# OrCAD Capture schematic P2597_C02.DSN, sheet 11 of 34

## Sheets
11 23_12V BOOST: size Custom
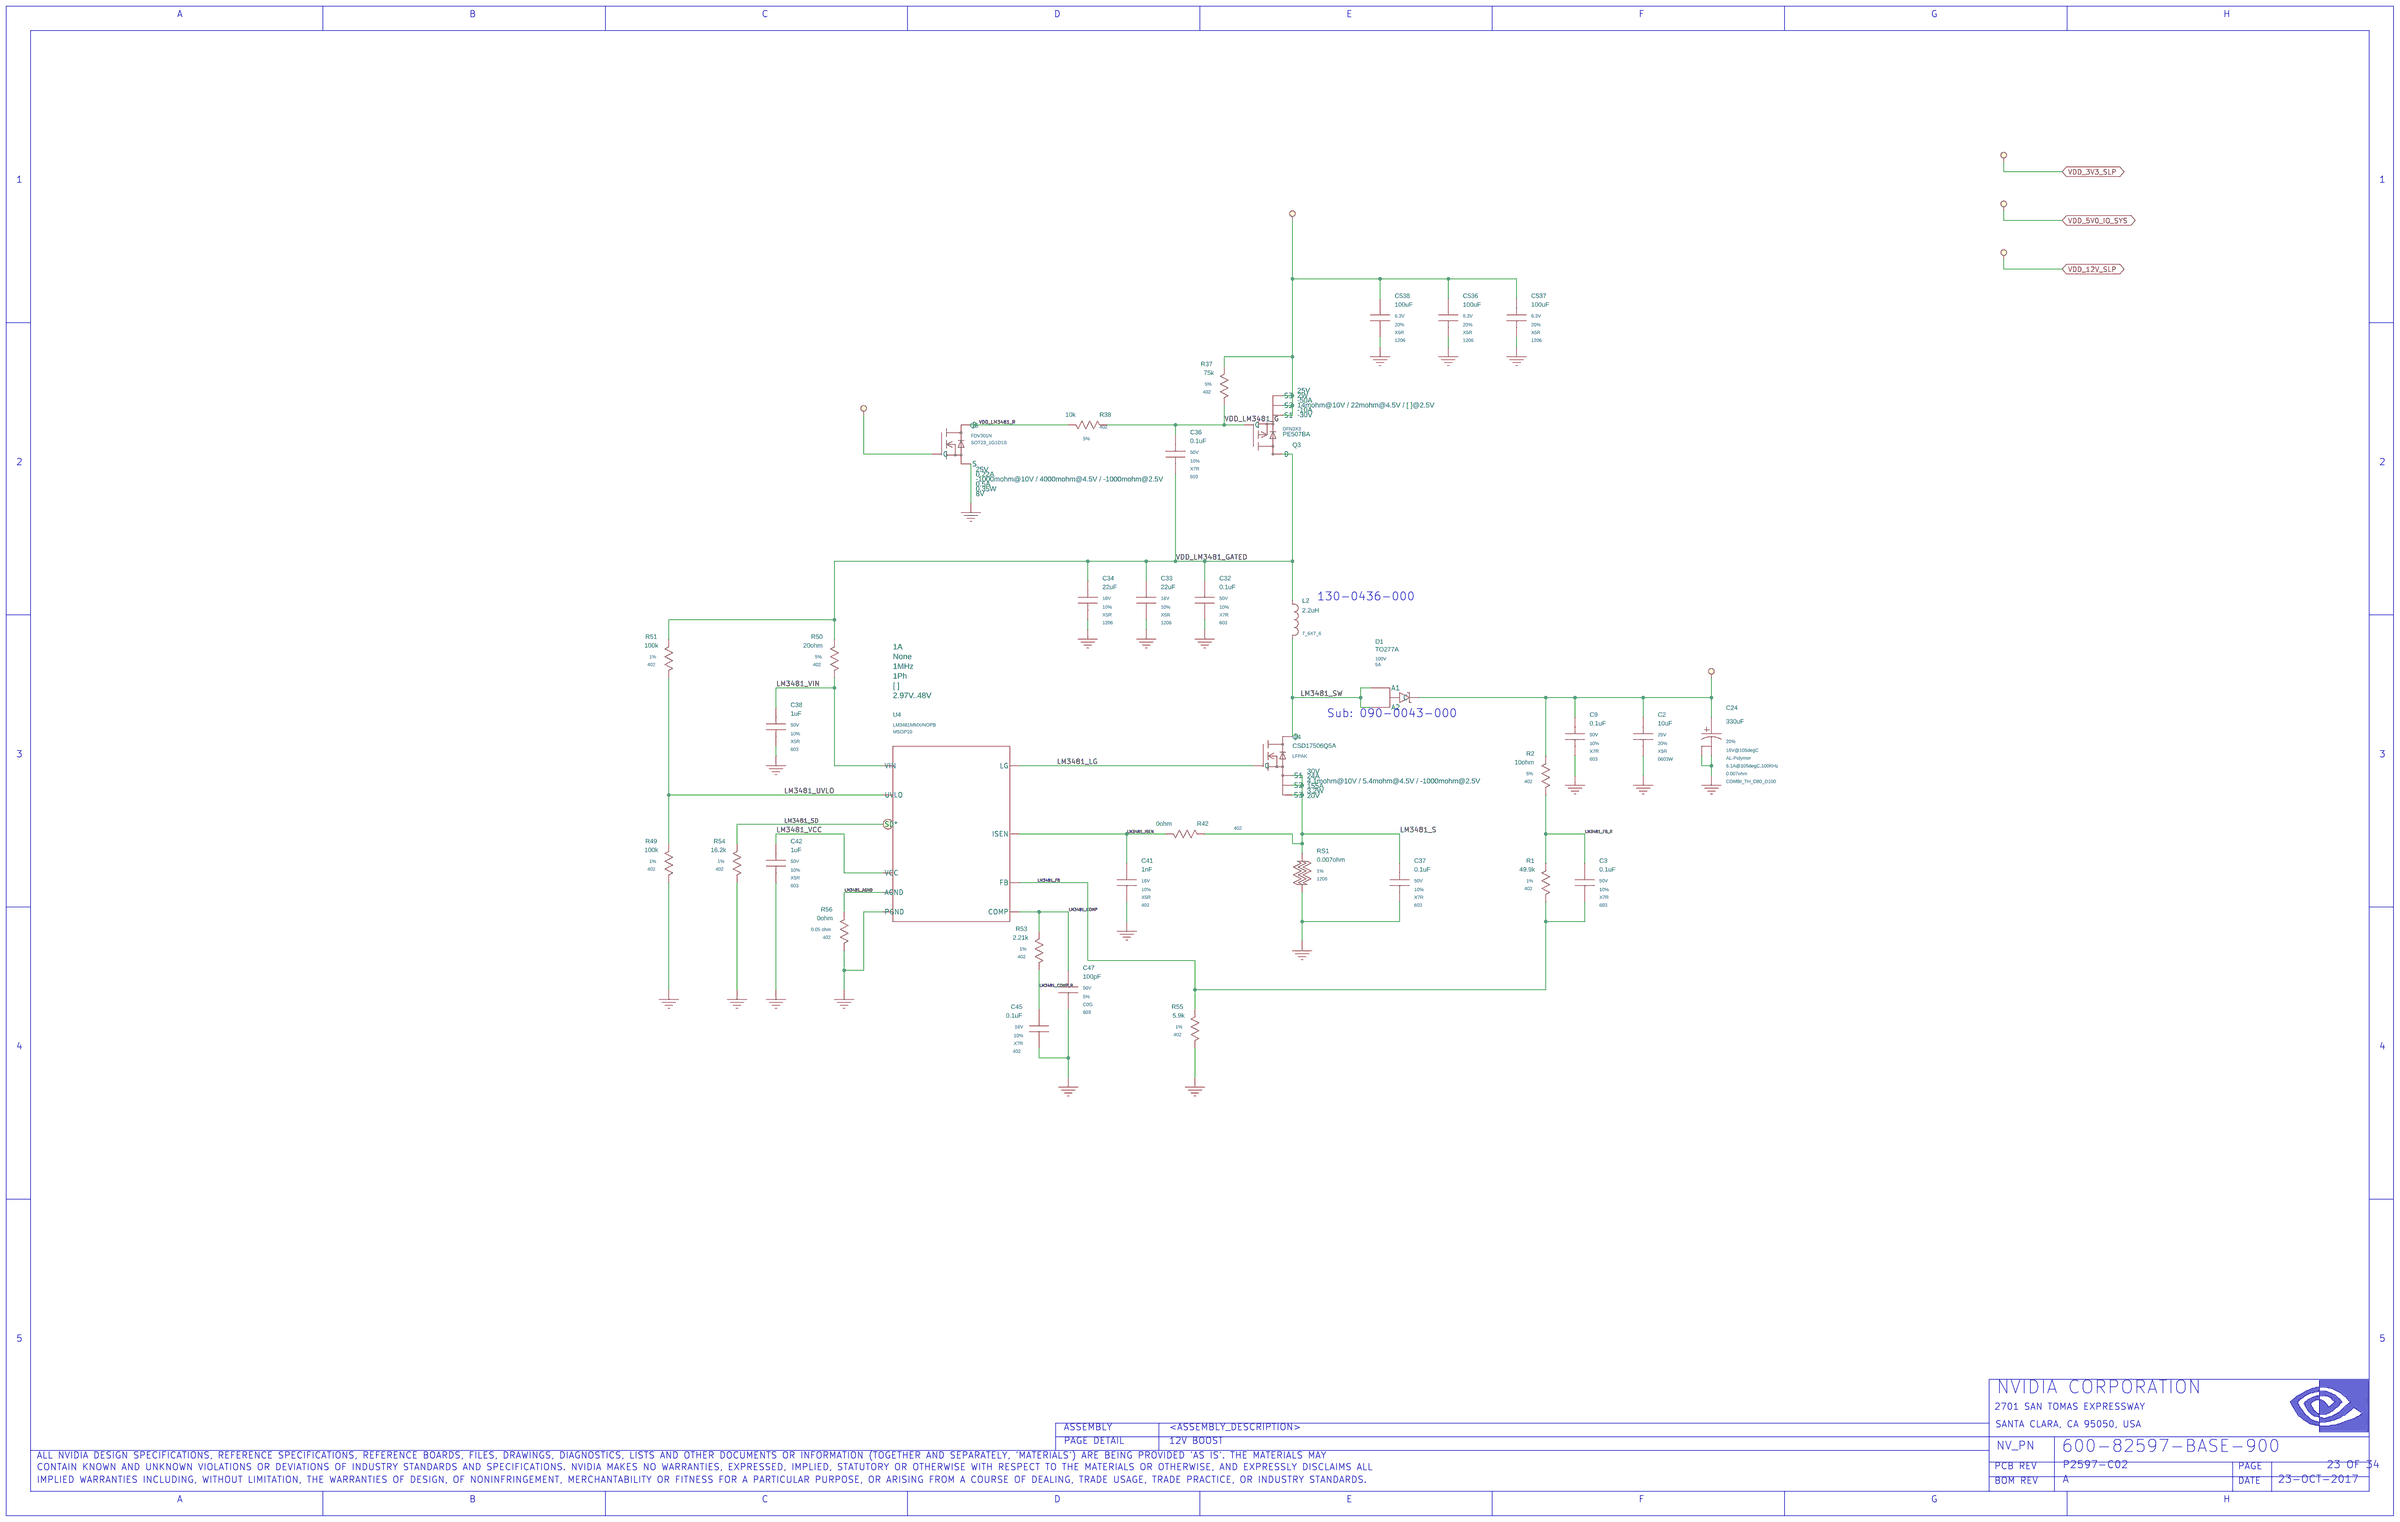
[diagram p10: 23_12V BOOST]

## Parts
C2  10uF  [0603_LARGE]
C3  0.1uF  [603]
C9  0.1uF  [603]
C24  330uF  [MULTI_CAP_TH_D080P035_D100P050]
C32  0.1uF  [603]
C33  22uF  [1206]
C34  22uF  [1206]
C36  0.1uF  [603]
C37  0.1uF  [603]
C38  1uF  [603]
C41  1nF  [402]
C42  1uF  [603]
C45  0.1uF  [402]
C47  100pF  [603]
C536  100uF  [1206]
C537  100uF  [1206]
C538  100uF  [1206]
D1  D_SCHOTTKY_3PIN_AA  [DIODE_SMD_TO277A]
L2  2.2uH  [IND_NONRKO_SMD_076X076]
Q3  Q_FET_P_ENH  [DFET_SMD_032X033]
Q4  Q_FET_N_ENH  [MULTI_SMD_SOT669_LFPAK_B]
Q5  Q_FET_N_ENH  [SOT23]
R1  49.9k  [402]
R2  10ohm  [402]
R37  75k  [402]
R38  10k  [402]
R42  0ohm  [402]
R49  100k  [402]
R50  20ohm  [402]
R51  100k  [402]
R53  2.21k  [402]
R54  16.2k  [402]
R55  5.9k  [402]
R56  0ohm  [402]
RS1  0.007ohm  [1206]
U4  1.275V  [XSOP10_P050_030X030]

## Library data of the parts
C2 = C: ASSEMBLY: VR_12V; CDS_LIB: discrete; CDS_PART_NAME: C_0603W-10UF,X5R,20%,25V,032-0421-000; CDS_PHYS_PART_NAME: C_0603W-10UF,X5R,20%,25V,032-0421-000-032-0421-000,10UF; CDS_SEC: 1; DEVICE_TYPENAME: C_0603W-10UFX5R2025V032-0421-000-032-0421-00010UF; DRAWING: @P2597_C02_LIB.P2597_C02(SCH_1):PAGE23; MAT: X5R; MAX_VOLTAGE: 25V; NV_PN: 032-0421-000; PACK_TYPE: 0603W; PATH: I43; PHYS_PAGE: 23; ROT: 0; SEC: 1; SIGNAL_MODEL: nv_cap; TOL: 20%; VER: 1; XY: (-3750,3850)
C3 = C: ASSEMBLY: VR_12V; CDS_LIB: discrete; CDS_PART_NAME: C_0603-0.1UF,X7R,10%,50V,036-0050-000; CDS_PHYS_PART_NAME: C_0603-0.1UF,X7R,10%,50V,036-0050-000-0.1UF,036-0050-000; CDS_SEC: 1; DEVICE_TYPENAME: C_0603-01UFX7R1050V036-0050-000-01UF036-0050-000; DRAWING: @P2597_C02_LIB.P2597_C02(SCH_1):PAGE23; MAT: X7R; MAX_VOLTAGE: 50V; NV_PN: 036-0050-000; PATH: I27; PHYS_PAGE: 23; ROT: 0; SEC: 1; SIGNAL_MODEL: nv_cap; TOL: 10%; VER: 1; XY: (-4050,3100)
C9 = C: ASSEMBLY: VR_12V; CDS_LIB: discrete; CDS_PART_NAME: C_0603-0.1UF,X7R,10%,50V,036-0050-000; CDS_PHYS_PART_NAME: C_0603-0.1UF,X7R,10%,50V,036-0050-000-0.1UF,036-0050-000; CDS_SEC: 1; DEVICE_TYPENAME: C_0603-01UFX7R1050V036-0050-000-01UF036-0050-000; DRAWING: @P2597_C02_LIB.P2597_C02(SCH_1):PAGE23; MAT: X7R; MAX_VOLTAGE: 50V; NV_PN: 036-0050-000; PATH: I40; PHYS_PAGE: 23; ROT: 0; SEC: 1; SIGNAL_MODEL: nv_cap; TOL: 10%; VER: 1; XY: (-4100,3850)
C24 = C_POL#1: ASSEMBLY: VR_12V; CDS_LIB: discrete; CDS_PART_NAME: C_POL_COMBI_TH_D80_D100-330UF,AL-POLYMER,20%,16V@105DEGC,0.007OHM,9.999UH,6.1A@105DEGC,100KHZ,041-0065-000; CDS_PHYS_PART_NAME: C_POL_COMBI_TH_D80_D100-330UF,AL-POLYMER,20%,16V@105DEGC,0.007OHM,9.999UH,6.1A@105DEGC,100KHZ,041-0065-000-041-0065-000,330UF; CDS_SEC: 1; CHIPS_PART_NAME: C_POL; DEVICE_TYPENAME: C_POL_COMBI_TH_D80_D100-330UFAL-POLYMER2016V105DEGC0007OHM9999UH61A105DEGC100KHZ041-0065-000-041-0065-000330UF; DRAWING: @P2597_C02_LIB.P2597_C02(SCH_1):PAGE23; ESL: 9.999uH; ESR: 0.007ohm; MAT: AL-Polymer; MAX_VOLTAGE: 16V@105degC; NV_PN: 041-0065-000; PACK_TYPE: COMBI_TH_D80_D100; PATH: I44; PHYS_PAGE: 23; RIPPLE_CURRENT: 6.1A@105degC,100KHz; ROT: 0; SEC: 1; SEC_TYPE: COMBI_TH_D80_D100; SIGNAL_MODEL: nv_capp_3p; TOL: 20%; VER: 3; XY: (-3400,3850)
C32 = C: ASSEMBLY: VR_12V; CDS_LIB: discrete; CDS_PART_NAME: C_0603-0.1UF,X7R,10%,50V,036-0050-000; CDS_PHYS_PART_NAME: C_0603-0.1UF,X7R,10%,50V,036-0050-000-0.1UF,036-0050-000; CDS_SEC: 1; DEVICE_TYPENAME: C_0603-01UFX7R1050V036-0050-000-01UF036-0050-000; DRAWING: @P2597_C02_LIB.P2597_C02(SCH_1):PAGE23; MAT: X7R; MAX_VOLTAGE: 50V; NV_PN: 036-0050-000; PATH: I35; PHYS_PAGE: 23; ROT: 0; SEC: 1; SIGNAL_MODEL: nv_cap; TOL: 10%; VER: 1; XY: (-6000,4550)
C33 = C: ASSEMBLY: VR_12V; CDS_LIB: discrete; CDS_PART_NAME: C_1206-22UF,X5R,10%,16V,039-0158-000; CDS_PHYS_PART_NAME: C_1206-22UF,X5R,10%,16V,039-0158-000-039-0158-000,22UF; CDS_SEC: 1; DEVICE_TYPENAME: C_1206-22UFX5R1016V039-0158-000-039-0158-00022UF; DRAWING: @P2597_C02_LIB.P2597_C02(SCH_1):PAGE23; MAT: X5R; MAX_VOLTAGE: 16V; NV_PN: 039-0158-000; PATH: I33; PHYS_PAGE: 23; ROT: 0; SEC: 1; SIGNAL_MODEL: nv_cap; TOL: 10%; VER: 1; XY: (-6300,4550)
C34 = C: ASSEMBLY: VR_12V; CDS_LIB: discrete; CDS_PART_NAME: C_1206-22UF,X5R,10%,16V,039-0158-000; CDS_PHYS_PART_NAME: C_1206-22UF,X5R,10%,16V,039-0158-000-039-0158-000,22UF; CDS_SEC: 1; DEVICE_TYPENAME: C_1206-22UFX5R1016V039-0158-000-039-0158-00022UF; DRAWING: @P2597_C02_LIB.P2597_C02(SCH_1):PAGE23; MAT: X5R; MAX_VOLTAGE: 16V; NV_PN: 039-0158-000; PATH: I28; PHYS_PAGE: 23; ROT: 0; SEC: 1; SIGNAL_MODEL: nv_cap; TOL: 10%; VER: 1; XY: (-6600,4550)
C36 = C: ASSEMBLY: VR_12V; CDS_LIB: discrete; CDS_PART_NAME: C_0603-0.1UF,X7R,10%,50V,036-0050-000; CDS_PHYS_PART_NAME: C_0603-0.1UF,X7R,10%,50V,036-0050-000-0.1UF,036-0050-000; CDS_SEC: 1; DEVICE_TYPENAME: C_0603-01UFX7R1050V036-0050-000-01UF036-0050-000; DRAWING: @P2597_C02_LIB.P2597_C02(SCH_1):PAGE23; MAT: X7R; MAX_VOLTAGE: 50V; NV_PN: 036-0050-000; PATH: I55; PHYS_PAGE: 23; ROT: 0; SEC: 1; SIGNAL_MODEL: nv_cap; TOL: 10%; VER: 1; XY: (-6150,5300)
C37 = C: ASSEMBLY: VR_12V; CDS_LIB: discrete; CDS_PART_NAME: C_0603-0.1UF,X7R,10%,50V,036-0050-000; CDS_PHYS_PART_NAME: C_0603-0.1UF,X7R,10%,50V,036-0050-000-0.1UF,036-0050-000; CDS_SEC: 1; DEVICE_TYPENAME: C_0603-01UFX7R1050V036-0050-000-01UF036-0050-000; DRAWING: @P2597_C02_LIB.P2597_C02(SCH_1):PAGE23; MAT: X7R; MAX_VOLTAGE: 50V; NV_PN: 036-0050-000; PATH: I25; PHYS_PAGE: 23; ROT: 0; SEC: 1; SIGNAL_MODEL: nv_cap; TOL: 10%; VER: 1; XY: (-5000,3100)
C38 = C: ASSEMBLY: VR_12V; CDS_LIB: discrete; CDS_PART_NAME: C_0603-1UF,X5R,10%,50V,039-0222-000; CDS_PHYS_PART_NAME: C_0603-1UF,X5R,10%,50V,039-0222-000-039-0222-000,1UF; CDS_SEC: 1; DEVICE_TYPENAME: C_0603-1UFX5R1050V039-0222-000-039-0222-0001UF; DRAWING: @P2597_C02_LIB.P2597_C02(SCH_1):PAGE23; MAT: X5R; MAX_VOLTAGE: 50V; NV_PN: 039-0222-000; PATH: I12; PHYS_PAGE: 23; ROT: 0; SEC: 1; SIGNAL_MODEL: nv_cap; TOL: 10%; VER: 1; XY: (-8200,3900)
C41 = C: ASSEMBLY: VR_12V; CDS_LIB: discrete; CDS_PART_NAME: C_0402-1NF,X5R,10%,16V,039-0023-000; CDS_PHYS_PART_NAME: C_0402-1NF,X5R,10%,16V,039-0023-000-039-0023-000,1NF; CDS_SEC: 1; DEVICE_TYPENAME: C_0402-1NFX5R1016V039-0023-000-039-0023-0001NF; DRAWING: @P2597_C02_LIB.P2597_C02(SCH_1):PAGE23; MAT: X5R; MAX_VOLTAGE: 16V; NV_PN: 039-0023-000; PATH: I20; PHYS_PAGE: 23; ROT: 0; SEC: 1; SIGNAL_MODEL: nv_cap; TOL: 10%; VER: 1; XY: (-6400,3100)
C42 = C: ASSEMBLY: VR_12V; CDS_LIB: discrete; CDS_PART_NAME: C_0603-1UF,X5R,10%,50V,039-0222-000; CDS_PHYS_PART_NAME: C_0603-1UF,X5R,10%,50V,039-0222-000-039-0222-000,1UF; CDS_SEC: 1; DEVICE_TYPENAME: C_0603-1UFX5R1050V039-0222-000-039-0222-0001UF; DRAWING: @P2597_C02_LIB.P2597_C02(SCH_1):PAGE23; MAT: X5R; MAX_VOLTAGE: 50V; NV_PN: 039-0222-000; PATH: I5; PHYS_PAGE: 23; ROT: 0; SEC: 1; SIGNAL_MODEL: nv_cap; TOL: 10%; VER: 1; XY: (-8200,3200)
C45 = C: ASSEMBLY: VR_12V; CDS_LIB: discrete; CDS_PART_NAME: C_0402-0.1UF,X7R,10%,16V,036-0014-000; CDS_PHYS_PART_NAME: C_0402-0.1UF,X7R,10%,16V,036-0014-000-0.1UF,036-0014-000; CDS_SEC: 1; DEVICE_TYPENAME: C_0402-01UFX7R1016V036-0014-000-01UF036-0014-000; DRAWING: @P2597_C02_LIB.P2597_C02(SCH_1):PAGE23; MAT: X7R; MAX_VOLTAGE: 16V; NV_PN: 036-0014-000; PATH: I62; PHYS_PAGE: 23; ROT: 2; SEC: 1; SIGNAL_MODEL: nv_cap; TOL: 10%; VER: 1; XY: (-6850,2350)
C47 = C: ASSEMBLY: VR_12V; CDS_LIB: discrete; CDS_PART_NAME: C_0603-100PF,C0G,5%,50V,035-0040-000; CDS_PHYS_PART_NAME: C_0603-100PF,C0G,5%,50V,035-0040-000-035-0040-000,100PF; CDS_SEC: 1; DEVICE_TYPENAME: C_0603-100PFC0G550V035-0040-000-035-0040-000100PF; DRAWING: @P2597_C02_LIB.P2597_C02(SCH_1):PAGE23; MAT: C0G; MAX_VOLTAGE: 50V; NV_PN: 035-0040-000; PATH: I61; PHYS_PAGE: 23; ROT: 0; SEC: 1; SIGNAL_MODEL: nv_cap; TOL: 5%; VER: 1; XY: (-6700,2550)
C536 = C: ASSEMBLY: VR_12V; CDS_LIB: discrete; CDS_PART_NAME: C_1206-100UF,X5R,20%,6.3V,039-0148-000; CDS_PHYS_PART_NAME: C_1206-100UF,X5R,20%,6.3V,039-0148-000-039-0148-000,100UF; CDS_SEC: 1; DEVICE_TYPENAME: C_1206-100UFX5R2063V039-0148-000-039-0148-000100UF; DRAWING: @P2597_C02_LIB.P2597_C02(SCH_1):PAGE23; MAT: X5R; MAX_VOLTAGE: 6.3V; NV_PN: 039-0148-000; PATH: I69; PHYS_PAGE: 23; ROT: 0; SEC: 1; SIGNAL_MODEL: nv_cap; TOL: 20%; VER: 1; XY: (-4750,6000)
C537 = C: ASSEMBLY: VR_12V; CDS_LIB: discrete; CDS_PART_NAME: C_1206-100UF,X5R,20%,6.3V,039-0148-000; CDS_PHYS_PART_NAME: C_1206-100UF,X5R,20%,6.3V,039-0148-000-039-0148-000,100UF; CDS_SEC: 1; DEVICE_TYPENAME: C_1206-100UFX5R2063V039-0148-000-039-0148-000100UF; DRAWING: @P2597_C02_LIB.P2597_C02(SCH_1):PAGE23; MAT: X5R; MAX_VOLTAGE: 6.3V; NV_PN: 039-0148-000; PATH: I73; PHYS_PAGE: 23; ROT: 0; SEC: 1; SIGNAL_MODEL: nv_cap; TOL: 20%; VER: 1; XY: (-4400,6000)
C538 = C: ASSEMBLY: VR_12V; CDS_LIB: discrete; CDS_PART_NAME: C_1206-100UF,X5R,20%,6.3V,039-0148-000; CDS_PHYS_PART_NAME: C_1206-100UF,X5R,20%,6.3V,039-0148-000-039-0148-000,100UF; CDS_SEC: 1; DEVICE_TYPENAME: C_1206-100UFX5R2063V039-0148-000-039-0148-000100UF; DRAWING: @P2597_C02_LIB.P2597_C02(SCH_1):PAGE23; MAT: X5R; MAX_VOLTAGE: 6.3V; NV_PN: 039-0148-000; PATH: I71; PHYS_PAGE: 23; ROT: 0; SEC: 1; SIGNAL_MODEL: nv_cap; TOL: 20%; VER: 1; XY: (-5100,6000)
D1 = D_SCHOTTKY_3PIN_AA: ASSEMBLY: VR_12V; CDS_LIB: discrete; CDS_PART_NAME: D_SCHOTTKY_3PIN_AA_SMPC-TO277A,1 PAIR - COMMON CATHODE,100V,150A,0.88V@5A,5A,090-0043-000; CDS_PHYS_PART_NAME: D_SCHOTTKY_3PIN_AA_SMPC-TO277A,1 PAIR - COMMON CATHODE,100V,150A,0.88V@5A,5A,090-0043-000-090-0043-000; CDS_SEC: 1; CONFIGURATION: 1 Pair - Common Cathode; CONTINUOUS_CURRENT: 5A; DEVICE_TYPENAME: D_SCHOTTKY_3PIN_AA_SMPC-TO277A1PAIR-COMMONCATHODE100V150A088V5A5A090-0043-000-090-0043-000; DRAWING: @P2597_C02_LIB.P2597_C02(SCH_1):PAGE23; FORWARD_VOLTAGE: 0.88V@5A; MAX_CURRENT: 150A; MAX_VOLTAGE: 100V; NV_NAME: TO277A; NV_PN: 090-0043-000; PACK_TYPE: SMPC; PATH: I68; PHYS_PAGE: 23; ROT: 0; SEC: 1; SEC_TYPE: SMPC; VER: 2; XY: (-5050,4050)
L2 = L#1: ACOUSTIC_MARGIN: 0decibel; ASSEMBLY: VR_12V; CDS_LIB: discrete; CDS_PART_NAME: L_7_6X7_6-2.2UH,ALLOY CORE,20%,10A,10A,0.0132OHM,[ ]@[ ],[ ],0DECIBEL,130-0436-000; CDS_PHYS_PART_NAME: L_7_6X7_6-2.2UH,ALLOY CORE,20%,10A,10A,0.0132OHM,[ ]@[ ],[ ],0DECIBEL,130-0436-000-130-0436-000,2.2UH; CDS_SEC: 1; CHIPS_PART_NAME: L; CONTINUOUS_CURRENT: 10A; DC_RESISTANCE: 0.0132ohm; DEVICE_TYPENAME: L_7_6X7_6-22UHALLOYCORE2010A10A00132OHM0DECIBEL130-0436-000-130-0436-00022UH; DRAWING: @P2597_C02_LIB.P2597_C02(SCH_1):PAGE23; MAT: ALLOY CORE; MAX_CURRENT: 10A; NV_PN: 130-0436-000; PACK_TYPE: 7_6X7_6; PATH: I36; PHYS_PAGE: 23; Q: [ ]@[ ]; ROT: 0; SEC: 1; SEC_TYPE: 7_6X7_6; SELF_RESONANCE_FREQ: [ ]; SIGNAL_MODEL: nv_ind; TOL: 20%; VER: 2; XY: (-5550,4450)
Q3 = Q_FET_P_ENH#1: ASSEMBLY: VR_12V; CDS_LIB: discrete; CDS_PART_NAME: Q_FET_P_ENH_DFN3X3-PE507BA,-30V,14MOHM@10V / 22MOHM@4.5V / [ ]@2.5V,-10A,-50A,25V,2W,49.1NC@10V / 0NC@4.5V / [ ]@2.5V,300-1028A; CDS_PHYS_PART_NAME: Q_FET_P_ENH_DFN3X3-PE507BA,-30V,14MOHM@10V / 22MOHM@4.5V / [ ]@2.5V,-10A,-50A,25V,2W,49.1NC@10V / 0NC@4.5V / [ ]@2.5V,300-1028B; CDS_SEC: 1; CONTINUOUS_CURRENT: -10A; DEVICE_TYPENAME: Q_FET_P_ENH_DFN3X3-PE507BA-30V14MOHM10V22MOHM45V25V-10A-50A25V2W491NC10V0NC45V25V300-1028B; DRAWING: @P2597_C02_LIB.P2597_C02(SCH_1):PAGE23; MAX_CURRENT: -50A; MAX_VOLTAGE: -30V; MAX_WATTAGE: 2W; NV_NAME: PE507BA; NV_PN: 300-1028-000; PACK_TYPE: DFN3X3; PATH: I52; PHYS_PAGE: 23; Q_G: 49.1nC@10V / 0nC@4.5V / [ ]@2.5V; ROT: 6; R_DS_ON: 14mohm@10V / 22mohm@4.5V / [ ]@2.5V; SEC: 1; VER: 8; V_BE_GS: 25V; XY: (-5700,5400)
Q4 = Q_FET_N_ENH#3: ASSEMBLY: VR_12V; CDS_LIB: discrete; CDS_PART_NAME: Q_FET_N_ENH_LFPAK-CSD17506Q5A,30V,4.1MOHM@10V / 5.4MOHM@4.5V / -1000MOHM@2.5V,24A,155A,20V,3.2W,[ ]@10V / [ ]@4.5V / [ ]@2.5V,A; CDS_PHYS_PART_NAME: Q_FET_N_ENH_LFPAK-CSD17506Q5A,30V,4.1MOHM@10V / 5.4MOHM@4.5V / -1000MOHM@2.5V,24A,155A,20V,3.2W,[ ]@10V / [ ]@4.5V / [ ]@2.5V,B; CDS_SEC: 1; CONTINUOUS_CURRENT: 24A; DEVICE_TYPENAME: Q_FET_N_ENH_LFPAK-CSD17506Q5A30V41MOHM10V54MOHM45V-1000MOHM25V24A155A20V32W10V45V25VB; DRAWING: @P2597_C02_LIB.P2597_C02(SCH_1):PAGE23; MAX_CURRENT: 155A; MAX_VOLTAGE: 30V; MAX_WATTAGE: 3.2W; NV_NAME: CSD17506Q5A; NV_PN: 300-0608-000; PACK_TYPE: LFPAK; PATH: I65; PHYS_PAGE: 23; Q_G: [ ]@10V / [ ]@4.5V / [ ]@2.5V; ROT: 0; R_DS_ON: 4.1mohm@10V / 5.4mohm@4.5V / -1000mohm@2.5V; SEC: 1; SEC_TYPE: LFPAK; VER: 5; V_BE_GS: 20V; XY: (-5650,3750)
Q5 = Q_FET_N_ENH#2: ASSEMBLY: VR_12V; CDS_LIB: discrete; CDS_PART_NAME: Q_FET_N_ENH_SOT23_1G1D1S-FDV301N,25V,-1000MOHM@10V / 4000MOHM@4.5V / -1000MOHM@2.5V,0.22A,0.5A,8V,0.35W,[ ]@10V / [ ]@4.5V / [A; CDS_PHYS_PART_NAME: Q_FET_N_ENH_SOT23_1G1D1S-FDV301N,25V,-1000MOHM@10V / 4000MOHM@4.5V / -1000MOHM@2.5V,0.22A,0.5A,8V,0.35W,[ ]@10V / [ ]@4.5V / [B; CDS_SEC: 1; CONTINUOUS_CURRENT: 0.22A; CaptureCellPackProp: Q_FET_N_ENH__sym_2##2; DEVICE_TYPENAME: Q_FET_N_ENH_SOT23_1G1D1S-FDV301N25V-1000MOHM10V4000MOHM45V-1000MOHM25V022A05A8V035W10V45VB; DRAWING: @P2597_C02_LIB.P2597_C02(SCH_1):PAGE23; MAX_CURRENT: 0.5A; MAX_VOLTAGE: 25V; MAX_WATTAGE: 0.35W; NV_NAME: FDV301N; NV_PN: 300-0494-000; PACK_TYPE: SOT23_1G1D1S; PATH: I63; PHYS_PAGE: 23; Q_G: [ ]@10V / [ ]@4.5V / [ ]@2.5V; ROT: 0; R_DS_ON: -1000mohm@10V / 4000mohm@4.5V / -1000mohm@2.5V; SEC: 1; VER: 2; V_BE_GS: 8V; XY: (-7300,5350)
R1 = R#1: ASSEMBLY: VR_12V; CDS_LIB: discrete; CDS_PART_NAME: R_0402-49.9K,1 %,62.5MW,195-0340-000; CDS_PHYS_PART_NAME: R_0402-49.9K,1 %,62.5MW,195-0340-000-195-0340-000,49.9K; CDS_SEC: 1; CHIPS_PART_NAME: R; DEVICE_TYPENAME: R_0402-499K1625MW195-0340-000-195-0340-000499K; DRAWING: @P2597_C02_LIB.P2597_C02(SCH_1):PAGE23; MAX_WATTAGE: 62.5mW; NV_PN: 195-0340-000; PATH: I26; PHYS_PAGE: 23; ROT: 2; SEC: 1; SIGNAL_MODEL: nv_res; TOL: 1%; VER: 2; XY: (-4250,3100)
R2 = R#1: ASSEMBLY: VR_12V; CDS_LIB: discrete; CDS_PART_NAME: R_0402-10OHM,5 %,62.5MW,195-0483-000; CDS_PHYS_PART_NAME: R_0402-10OHM,5 %,62.5MW,195-0483-000-10OHM,195-0483-000; CDS_SEC: 1; CHIPS_PART_NAME: R; DEVICE_TYPENAME: R_0402-10OHM5625MW195-0483-000-10OHM195-0483-000; DRAWING: @P2597_C02_LIB.P2597_C02(SCH_1):PAGE23; MAX_WATTAGE: 62.5mW; NV_PN: 195-0483-000; PATH: I46; PHYS_PAGE: 23; ROT: 2; SEC: 1; SIGNAL_MODEL: nv_res; TOL: 5%; VER: 2; XY: (-4250,3650)
R37 = R#1: ASSEMBLY: VR_12V; CDS_LIB: discrete; CDS_PART_NAME: R_0402-75K,5 %,62.5MW,195-0634-000; CDS_PHYS_PART_NAME: R_0402-75K,5 %,62.5MW,195-0634-000-195-0634-000,75K; CDS_SEC: 1; CHIPS_PART_NAME: R; DEVICE_TYPENAME: R_0402-75K5625MW195-0634-000-195-0634-00075K; DRAWING: @P2597_C02_LIB.P2597_C02(SCH_1):PAGE23; MAX_WATTAGE: 62.5mW; NV_PN: 195-0634-000; PATH: I54; PHYS_PAGE: 23; ROT: 2; SEC: 1; SIGNAL_MODEL: nv_res; TOL: 5%; VER: 2; XY: (-5900,5650)
R38 = R: ASSEMBLY: VR_12V; CDS_LIB: discrete; CDS_PART_NAME: R_0402-10K,5 %,62.5MW,195-0486-000; CDS_PHYS_PART_NAME: R_0402-10K,5 %,62.5MW,195-0486-000-10K,195-0486-000; CDS_SEC: 1; DEVICE_TYPENAME: R_0402-10K5625MW195-0486-000-10K195-0486-000; DRAWING: @P2597_C02_LIB.P2597_C02(SCH_1):PAGE23; MAX_WATTAGE: 62.5mW; NV_PN: 195-0486-000; PATH: I60; PHYS_PAGE: 23; ROT: 2; SEC: 1; SIGNAL_MODEL: nv_res; TOL: 5%; VER: 1; XY: (-6600,5450)
R42 = R: ASSEMBLY: VR_12V; CDS_LIB: discrete; CDS_PART_NAME: R_0402-0OHM,0.05 OHM,62.5MW,195-2655-000; CDS_PHYS_PART_NAME: R_0402-0OHM,0.05 OHM,62.5MW,195-2655-000-0OHM,195-2655-000; CDS_SEC: 1; DEVICE_TYPENAME: R_0402-0OHM005OHM625MW195-2655-000-0OHM195-2655-000; DRAWING: @P2597_C02_LIB.P2597_C02(SCH_1):PAGE23; MAX_WATTAGE: 62.5mW; NV_PN: 195-2655-000; PATH: I30; PHYS_PAGE: 23; ROT: 2; SEC: 1; SIGNAL_MODEL: nv_res; TOL: 0.05 ohm; VER: 1; XY: (-6100,3350)
R49 = R#1: ASSEMBLY: VR_12V; CDS_LIB: discrete; CDS_PART_NAME: R_0402-100K,1 %,62.5MW,195-0005-000; CDS_PHYS_PART_NAME: R_0402-100K,1 %,62.5MW,195-0005-000-100K,195-0005-000; CDS_SEC: 1; CHIPS_PART_NAME: R; DEVICE_TYPENAME: R_0402-100K1625MW195-0005-000-100K195-0005-000; DRAWING: @P2597_C02_LIB.P2597_C02(SCH_1):PAGE23; MAX_WATTAGE: 62.5mW; NV_PN: 195-0005-000; PATH: I2; PHYS_PAGE: 23; ROT: 2; SEC: 1; SIGNAL_MODEL: nv_res; TOL: 1%; VER: 2; XY: (-8750,3200)
R50 = R#1: ASSEMBLY: VR_12V; CDS_LIB: discrete; CDS_PART_NAME: R_0402-20OHM,5 %,62.5MW,195-0533-000; CDS_PHYS_PART_NAME: R_0402-20OHM,5 %,62.5MW,195-0533-000-195-0533-000,20OHM; CDS_SEC: 1; CHIPS_PART_NAME: R; DEVICE_TYPENAME: R_0402-20OHM5625MW195-0533-000-195-0533-00020OHM; DRAWING: @P2597_C02_LIB.P2597_C02(SCH_1):PAGE23; MAX_WATTAGE: 62.5mW; NV_PN: 195-0533-000; PATH: I13; PHYS_PAGE: 23; ROT: 2; SEC: 1; SIGNAL_MODEL: nv_res; TOL: 5%; VER: 2; XY: (-7900,4250)
R51 = R#1: ASSEMBLY: VR_12V; CDS_LIB: discrete; CDS_PART_NAME: R_0402-100K,1 %,62.5MW,195-0005-000; CDS_PHYS_PART_NAME: R_0402-100K,1 %,62.5MW,195-0005-000-100K,195-0005-000; CDS_SEC: 1; CHIPS_PART_NAME: R; DEVICE_TYPENAME: R_0402-100K1625MW195-0005-000-100K195-0005-000; DRAWING: @P2597_C02_LIB.P2597_C02(SCH_1):PAGE23; MAX_WATTAGE: 62.5mW; NV_PN: 195-0005-000; PATH: I10; PHYS_PAGE: 23; ROT: 2; SEC: 1; SIGNAL_MODEL: nv_res; TOL: 1%; VER: 2; XY: (-8750,4250)
R53 = R#1: ASSEMBLY: VR_12V; CDS_LIB: discrete; CDS_PART_NAME: R_0402-2.21K,1 %,62.5MW,195-0169-000; CDS_PHYS_PART_NAME: R_0402-2.21K,1 %,62.5MW,195-0169-000-195-0169-000,2.21K; CDS_SEC: 1; CHIPS_PART_NAME: R; DEVICE_TYPENAME: R_0402-221K1625MW195-0169-000-195-0169-000221K; DRAWING: @P2597_C02_LIB.P2597_C02(SCH_1):PAGE23; MAX_WATTAGE: 62.5mW; NV_PN: 195-0169-000; PATH: I19; PHYS_PAGE: 23; ROT: 2; SEC: 1; SIGNAL_MODEL: nv_res; TOL: 1%; VER: 2; XY: (-6850,2750)
R54 = R#1: ASSEMBLY: VR_12V; CDS_LIB: discrete; CDS_PART_NAME: R_0402-16.2K,1 %,62.5MW,195-0105-000; CDS_PHYS_PART_NAME: R_0402-16.2K,1 %,62.5MW,195-0105-000-16.2K,195-0105-000; CDS_SEC: 1; CHIPS_PART_NAME: R; DEVICE_TYPENAME: R_0402-162K1625MW195-0105-000-162K195-0105-000; DRAWING: @P2597_C02_LIB.P2597_C02(SCH_1):PAGE23; MAX_WATTAGE: 62.5mW; NV_PN: 195-0105-000; PATH: I6; PHYS_PAGE: 23; ROT: 2; SEC: 1; SIGNAL_MODEL: nv_res; TOL: 1%; VER: 2; XY: (-8400,3200)
R55 = R#1: ASSEMBLY: VR_12V; CDS_LIB: discrete; CDS_PART_NAME: R_0402-5.9K,1 %,62.5MW,195-0374-000; CDS_PHYS_PART_NAME: R_0402-5.9K,1 %,62.5MW,195-0374-000-195-0374-000,5.9K; CDS_SEC: 1; CHIPS_PART_NAME: R; DEVICE_TYPENAME: R_0402-59K1625MW195-0374-000-195-0374-00059K; DRAWING: @P2597_C02_LIB.P2597_C02(SCH_1):PAGE23; MAX_WATTAGE: 62.5mW; NV_PN: 195-0374-000; PATH: I22; PHYS_PAGE: 23; ROT: 2; SEC: 1; SIGNAL_MODEL: nv_res; TOL: 1%; VER: 2; XY: (-6050,2350)
R56 = R#1: ASSEMBLY: VR_12V; CDS_LIB: discrete; CDS_PART_NAME: R_0402-0OHM,0.05 OHM,62.5MW,195-2655-000; CDS_PHYS_PART_NAME: R_0402-0OHM,0.05 OHM,62.5MW,195-2655-000-0OHM,195-2655-000; CDS_SEC: 1; CHIPS_PART_NAME: R; DEVICE_TYPENAME: R_0402-0OHM005OHM625MW195-2655-000-0OHM195-2655-000; DRAWING: @P2597_C02_LIB.P2597_C02(SCH_1):PAGE23; MAX_WATTAGE: 62.5mW; NV_PN: 195-2655-000; PATH: I8; PHYS_PAGE: 23; ROT: 2; SEC: 1; SIGNAL_MODEL: nv_res; TOL: 0.05 ohm; VER: 2; XY: (-7850,2850)
RS1 = R_SENSE: ASSEMBLY: VR_12V; CDS_LIB: discrete; CDS_PART_NAME: R_SENSE_1206-0.007OHM,1%,0.5W,[ ],215-0064-000; CDS_PHYS_PART_NAME: R_SENSE_1206-0.007OHM,1%,0.5W,[ ],215-0064-000-0.007OHM,215-0064-000; CDS_SEC: 1; DEVICE_TYPENAME: R_SENSE_1206-0007OHM105W215-0064-000-0007OHM215-0064-000; DRAWING: @P2597_C02_LIB.P2597_C02(SCH_1):PAGE23; MAX_WATTAGE: 0.5W; NV_PN: 215-0064-000; PATH: I66; PHYS_PAGE: 23; ROT: 0; SEC: 1; SIGNAL_MODEL: nv_res_noxnet; TEMP_COEF: [ ]; TOL: 1%; VER: 2; XY: (-5500,3150)
U4 = U_DCDC_BOOST_LM3481: ASSEMBLY: VR_12V; CDS_LIB: power_supply; CDS_PART_NAME: U_DCDC_BOOST_LM3481_MSOP10-LM3481MMX/NOPB,SEPIC,1PH,1MHZ,NONE,2.97V..48V,1.5%,1.275V,48V,1A,[ ],315-0763-000; CDS_PHYS_PART_NAME: U_DCDC_BOOST_LM3481_MSOP10-LM3481MMX/NOPB,SEPIC,1PH,1MHZ,NONE,2.97V..48V,1.5%,1.275V,48V,1A,[ ],315-0763-000-1.275V,315-0763-0A; CDS_SEC: 1; DEVICE_TYPENAME: U_DCDC_BOOST_LM3481_MSOP10-LM3481MMXNOPBSEPIC1PH1MHZNONE297V48V151275V48V1A315-0763-000-1275V315-0763-0A; DRAWING: @P2597_C02_LIB.P2597_C02(SCH_1):PAGE23; MAX_CURRENT: 1A; MAX_VOLTAGE: 48V; MAX_WATTAGE: [ ]; MODE: SEPIC; NV_NAME: LM3481MMX/NOPB; NV_PN: 315-0763-000; OUTPUT_VOLTAGE: 2.97V..48V; PACK_TYPE: MSOP10; PATH: I9; PHASES: 1Ph; PHYS_PAGE: 23; PROGRAMMABLE: None; ROT: 0; SEC: 1; SEC_TYPE: MSOP10; SWITCHING_FREQ: 1MHz; TOL: 1.50%; VER: 1; XY: (-7300,3350)

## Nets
GND: C2.2 C9.2 C24.2 C24.3 C32.2 C33.2 C34.2 C37.2 C38.2 C41.2 C42.2 C45.2 C47.2 C536.2 C537.2 C538.2 Q5.2(S) R49.2 R54.2 R55.2 R56.2 RS1.2 U4.7(PGND) ; also on sheet 1 2 3 4 5 6 7 9 10 12 13 14 15 16 17 18 19 20 21 22 23 24 25 26 30
VDD_3V3_SLP: Q5.1(G) ; also on sheet 4 5 16 17 20 21 22 25
VDD_5V0_IO_SYS: C536.1 C537.1 C538.1 Q3.1(S1) Q3.2(S2) Q3.3(S3) R37.1 ; also on sheet 4 5 6 9 12 16 17 18 20 22 26 30
VDD_12V_SLP: C2.1 C9.1 C24.1 D1.3(C) R2.1 ; also on sheet 12 22 25
VDD_LM3481_G: C36.1 Q3.4(G) R37.2 R38.1
VDD_LM3481_GATED: C32.1 C33.1 C34.1 C36.2 L2.1 Q3.5(D) R50.1 R51.1
VDD_LM3481_R: Q5.3(D) R38.2
LM3481_AGND: R56.1 U4.5(AGND)
LM3481_COMP: C47.1 R53.1 U4.3(COMP)
LM3481_COMP_R: C45.1 R53.2
LM3481_FB: C3.2 R1.2 R55.1 U4.4(FB)
LM3481_FB_R: C3.1 R1.1 R2.2
LM3481_ISEN: C41.1 R42.2 U4.1(ISEN)
LM3481_LG: Q4.4(G) U4.8(LG)
LM3481_S: C37.1 Q4.1(S1) Q4.2(S2) Q4.3(S3) R42.1 RS1.1
LM3481_SD: R54.1 U4.6(SD*)
LM3481_SW: D1.1(A1) D1.2(A2) L2.2 Q4.5(D)
LM3481_UVLO: R49.1 R51.2 U4.2(UVLO)
LM3481_VCC: C42.1 U4.9(VCC)
LM3481_VIN: C38.1 R50.2 U4.10(VIN)

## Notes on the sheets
sheet 11
- A
- B
- C
- D
- E
- F
- G
- H
- 1
- 1
- 2
- 2
- 130-0436-000
- Sub: 090-0043-000
- 3
- 3
- 4
- 4
- 5
- 5
- NVIDIA CORPORATION
- 2701 SAN TOMAS EXPRESSWAY
- ASSEMBLY
- <ASSEMBLY_DESCRIPTION>
- SANTA CLARA, CA 95050, USA
- PAGE DETAIL
- 12V BOOST
- NV_PN
- 600-82597-BASE-900
- ALL NVIDIA DESIGN SPECIFICATIONS, REFERENCE SPECIFICATIONS, REFERENCE BOARDS, FILES, DRAWINGS, DIAGNOSTICS, LISTS AND OTHER DOCUMENTS OR INFORMATION (TOGETHER AND SEPARATELY, 'MATERIALS') ARE BEING PROVIDED 'AS IS'. THE MATERIALS MAY
- CONTAIN KNOWN AND UNKNOWN VIOLATIONS OR DEVIATIONS OF INDUSTRY STANDARDS AND SPECIFICATIONS. NVIDIA MAKES NO WARRANTIES, EXPRESSED, IMPLIED, STATUTORY OR OTHERWISE WITH RESPECT TO THE MATERIALS OR OTHERWISE, AND EXPRESSLY DISCLAIMS ALL
- PCB REV
- P2597-C02
- PAGE
- 23 OF 34
- IMPLIED WARRANTIES INCLUDING, WITHOUT LIMITATION, THE WARRANTIES OF DESIGN, OF NONINFRINGEMENT, MERCHANTABILITY OR FITNESS FOR A PARTICULAR PURPOSE, OR ARISING FROM A COURSE OF DEALING, TRADE USAGE, TRADE PRACTICE, OR INDUSTRY STANDARDS.
- BOM REV
- A
- DATE
- 23-OCT-2017
- A
- B
- C
- D
- E
- F
- G
- H
